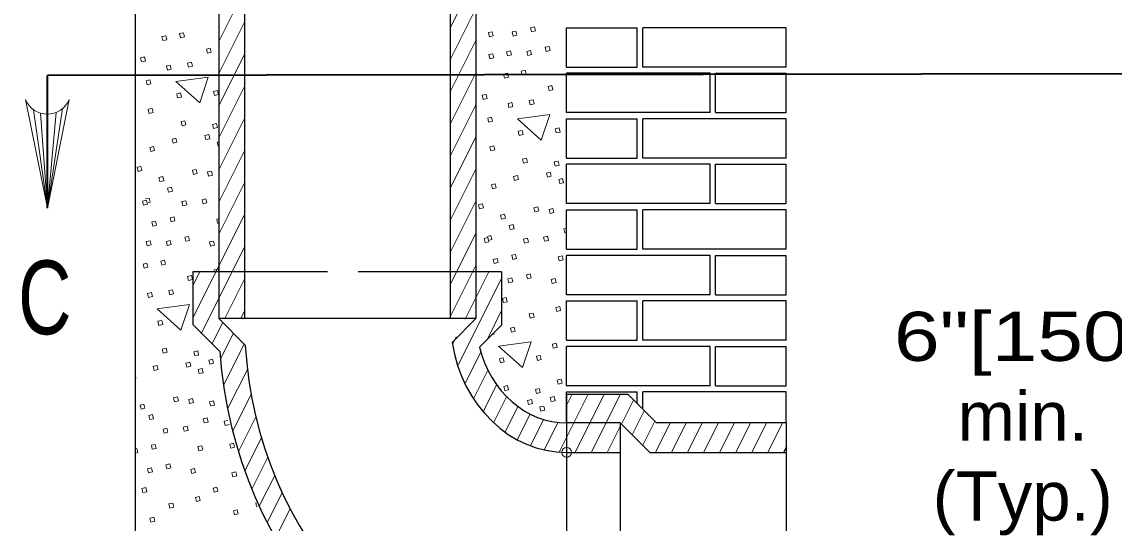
# Model space of a CAD drawing. Extents: x 750.7 to 784.7, y 860.1 to 882.1.
# Drawn here: x 760.221 to 763.779, y 864.968 to 866.601 of the extents above; entities that cross this region are included whole.
import ezdxf
from ezdxf.enums import TextEntityAlignment as Align

# ---------------------------------------------------------------- set-up
doc = ezdxf.new("R2010")
doc.units = 0
doc.header["$LTSCALE"] = 0.064
doc.header["$PDMODE"] = 32
doc.header["$PDSIZE"] = 0.032
doc.linetypes.add('LONG_DASHED', pattern=[7.5, 6, -1.5])
doc.layers.add('1', color=7, linetype='Continuous', lineweight=13)

msp = doc.modelspace()

# ---------------------------------------------------------------- linework, layer by layer
at = {"layer": '1', "lineweight": 25}
for p, q in [((760.59067, 862.95208), (760.59067, 875.03808)), ((760.862, 867.06925), (760.862, 865.6345)), ((760.94567, 867.089), (760.94567, 865.63483)), ((761.7, 866.80892), (761.7, 865.6345)), ((761.61633, 866.72725), (761.61633, 865.63483)), ((762.22558, 866.45333), (762.22558, 866.58133)), ((761.9955, 866.45333), (762.22558, 866.45333)), ((762.71083, 866.30508), (762.71083, 866.43308)), ((762.22558, 866.15675), (762.22558, 866.28483)), ((762.48075, 866.30508), (762.71083, 866.30508)), ((761.9955, 866.15675), (762.22558, 866.15675)), ((762.71083, 866.0085), (762.71083, 866.13658)), ((762.48075, 866.0085), (762.71083, 866.0085)), ((762.22558, 865.86025), (762.22558, 865.98833)), ((761.9955, 865.86025), (762.22558, 865.86025)), ((762.71083, 865.712), (762.71083, 865.84)), ((760.862, 865.78683), (760.77825, 865.78683)), ((760.77942, 865.61358), (760.77942, 865.78683)), ((761.78367, 865.78683), (761.7, 865.78683)), ((761.78367, 865.78683), (761.78367, 865.61317)), ((762.48075, 865.712), (762.71083, 865.712)), ((762.22558, 865.56375), (762.22558, 865.69175)), ((760.77942, 865.61358), (760.86583, 865.52725)), ((761.7, 865.6345), (760.862, 865.6345)), ((760.862, 865.6345), (760.94833, 865.54808)), ((761.7, 865.6345), (761.62242, 865.55683)), ((761.78367, 865.61317), (761.71142, 865.54092)), ((761.9955, 865.56375), (762.22558, 865.56375)), ((762.71083, 865.41542), (762.71083, 865.5435)), ((761.995, 865.3885), (761.995, 865.29225)), ((761.995, 865.3885), (762.19467, 865.3885)), ((762.19467, 865.3885), (762.28842, 865.29475)), ((762.22558, 865.35733), (762.22558, 865.39525)), ((762.24317, 865.34067), (762.24317, 865.39525)), ((762.48075, 865.41542), (762.71083, 865.41542)), ((762.17025, 865.29475), (761.99542, 865.29475)), ((762.17025, 865.29475), (762.17025, 864.331)), ((762.17025, 865.29475), (762.2665, 865.1985)), ((762.71083, 865.29475), (762.28842, 865.29475)), ((762.71083, 865.29475), (762.71083, 864.42725)), ((762.70292, 865.1985), (762.71083, 865.21442)), ((761.99542, 865.1985), (762.17025, 865.1985)), ((762.2665, 865.1985), (762.71083, 865.1985))]:
    msp.add_line(p, q, dxfattribs=at)
at = {"layer": '1'}
for p, q in [((761.61633, 866.58133), (761.7, 866.74875)), ((760.862, 866.53667), (760.94567, 866.704)), ((761.61633, 866.47675), (761.7, 866.64417)), ((760.862, 866.432), (760.94567, 866.59942)), ((761.61633, 866.37217), (761.7, 866.53958)), ((760.862, 866.32742), (760.94567, 866.49483)), ((761.61633, 866.26758), (761.7, 866.43492)), ((760.862, 866.22283), (760.94567, 866.39025)), ((760.25917, 866.31417), (760.30408, 865.9935)), ((760.35367, 866.31792), (760.30408, 865.9935)), ((761.61633, 866.163), (761.7, 866.33033)), ((760.28142, 866.30325), (760.30408, 865.9935)), ((760.33283, 866.30567), (760.30408, 865.9935)), ((760.30408, 866.3), (760.30408, 865.9935)), ((760.862, 866.11825), (760.94567, 866.28558)), ((761.61633, 866.05833), (761.7, 866.22575)), ((760.862, 866.01358), (760.94567, 866.181)), ((761.61633, 865.95375), (761.7, 866.12117)), ((760.862, 865.909), (760.94567, 866.07642)), ((760.6235, 866.02392), (760.63567, 866.02683)), ((761.61633, 865.84917), (761.7, 866.01658)), ((760.77825, 865.637), (760.94567, 865.97183)), ((761.61633, 865.74458), (761.7, 865.91192)), ((761.73617, 865.902), (761.74833, 865.90483)), ((760.805, 865.58583), (760.94567, 865.86717)), ((760.77825, 865.74158), (760.80092, 865.78683)), ((760.86008, 865.79567), (760.862, 865.78792)), ((761.61633, 865.63992), (761.7, 865.80733)), ((761.66508, 865.63292), (761.74208, 865.78683)), ((760.88158, 865.6345), (760.94567, 865.76258)), ((761.641, 865.48), (761.78367, 865.7655)), ((760.93433, 865.63533), (760.94567, 865.658)), ((761.73825, 865.56992), (761.78367, 865.66092)), ((760.84092, 865.55317), (760.87408, 865.6195)), ((760.86783, 865.50225), (760.90925, 865.58525)), ((761.62358, 865.54975), (761.636, 865.57458)), ((760.87775, 865.41758), (760.94467, 865.55142)), ((761.66433, 865.42217), (761.71575, 865.525)), ((760.89125, 865.34), (760.95558, 865.46867)), ((761.69208, 865.37308), (761.73875, 865.46633)), ((761.72333, 865.33092), (761.76725, 865.41875)), ((760.90767, 865.26817), (760.96767, 865.38833)), ((761.75767, 865.295), (761.8, 865.37975)), ((761.97133, 865.19942), (762.06467, 865.38617)), ((761.99483, 865.35108), (762.01342, 865.38833)), ((762.02317, 865.1985), (762.11692, 865.38608)), ((762.07542, 865.1985), (762.17033, 865.38833)), ((762.17392, 865.29092), (762.213, 865.36917)), ((761.79475, 865.26467), (761.8365, 865.34817)), ((761.83458, 865.23975), (761.8765, 865.3235)), ((762.20875, 865.25608), (762.2475, 865.3335)), ((760.92642, 865.20117), (760.98317, 865.31458)), ((761.87717, 865.22033), (761.92, 865.306)), ((761.92267, 865.20667), (761.96758, 865.2965)), ((762.12775, 865.1985), (762.16983, 865.28283)), ((762.24383, 865.22167), (762.283, 865.29992)), ((762.28458, 865.1985), (762.33267, 865.29475)), ((762.33692, 865.1985), (762.385, 865.29475)), ((762.38917, 865.1985), (762.43725, 865.29475)), ((762.44142, 865.1985), (762.48958, 865.29475)), ((762.49375, 865.1985), (762.54183, 865.29475)), ((762.546, 865.1985), (762.59417, 865.29475)), ((762.59833, 865.1985), (762.64642, 865.29475)), ((762.65058, 865.1985), (762.69867, 865.29475)), ((760.94733, 865.13825), (761.00133, 865.24642)), ((760.59067, 865.21033), (760.59508, 865.21142)), ((760.97, 865.07908), (761.02183, 865.18283)), ((760.99433, 865.02317), (761.04442, 865.12333)), ((761.02017, 864.97025), (761.06867, 865.06733)), ((761.04733, 864.92008), (761.09458, 865.01458))]:
    msp.add_line(p, q, dxfattribs=at)
at = {"layer": '1', "lineweight": 35}
for p in [(765.90858, 866.43392), (760.30408, 865.9935)]:
    msp.add_line(p, (760.30408, 866.42633), dxfattribs=at)
at = {"layer": '1', "linetype": 'LONG_DASHED', "lineweight": 25}
for p, q in [((761.7, 865.78683), (760.862, 865.78683)), ((761.995, 865.29225), (761.995, 864.3285))]:
    msp.add_line(p, q, dxfattribs=at)
at = {"layer": '1'}
for points in [[(760.74742, 866.56508), (760.75058, 866.55183), (760.738, 866.54883), (760.73483, 866.56208)], [(761.75325, 866.56833), (761.7565, 866.55508), (761.74392, 866.55208), (761.74075, 866.56533)], [(761.83042, 866.57067), (761.83358, 866.55742), (761.82108, 866.55442), (761.81783, 866.56767)], [(761.89058, 866.584), (761.89375, 866.57075), (761.88117, 866.56775), (761.878, 866.581)], [(760.68983, 866.5555), (760.69308, 866.54225), (760.6805, 866.53925), (760.67733, 866.5525)], [(760.83483, 866.51492), (760.83808, 866.50167), (760.8255, 866.49867), (760.82233, 866.51192)], [(761.75483, 866.49675), (761.758, 866.4835), (761.7455, 866.48058), (761.74225, 866.49375)], [(761.81233, 866.50642), (761.81558, 866.49317), (761.803, 866.49017), (761.79983, 866.50342)], [(761.87808, 866.50733), (761.88133, 866.49408), (761.86875, 866.49108), (761.86558, 866.50433)], [(761.93825, 866.52075), (761.94142, 866.5075), (761.92892, 866.5045), (761.92567, 866.51775)], [(760.62025, 866.48625), (760.6235, 866.473), (760.61092, 866.47), (760.60775, 866.48325)], [(760.70425, 866.45992), (760.7075, 866.44667), (760.69492, 866.44367), (760.69175, 866.45692)], [(760.77342, 866.46892), (760.77658, 866.45567), (760.76408, 866.45267), (760.76083, 866.46592)], [(760.82808, 866.42075), (760.72258, 866.40675), (760.80017, 866.33708)], [(761.8025, 866.4335), (761.80575, 866.42025), (761.79317, 866.41725), (761.79, 866.4305)], [(761.86008, 866.44317), (761.86325, 866.42992), (761.85067, 866.42692), (761.8475, 866.44017)], [(760.63817, 866.41183), (760.64133, 866.39858), (760.62875, 866.39558), (760.62558, 866.40883)], [(761.9475, 866.39292), (761.95075, 866.37967), (761.93817, 866.37667), (761.935, 866.38992)], [(760.73783, 866.369), (760.741, 866.35575), (760.72842, 866.35283), (760.72525, 866.366)], [(760.858, 866.37708), (760.86117, 866.36383), (760.84858, 866.36083), (760.84542, 866.37408)], [(761.73292, 866.36425), (761.73617, 866.351), (761.72358, 866.348), (761.72042, 866.36125)], [(760.64533, 866.31883), (760.6485, 866.30558), (760.63592, 866.30258), (760.63275, 866.31583)], [(761.81692, 866.33792), (761.82017, 866.32467), (761.80758, 866.32167), (761.80442, 866.33492)], [(761.88608, 866.34692), (761.88933, 866.33375), (761.87675, 866.33075), (761.8735, 866.34392)], [(760.75192, 866.27858), (760.75508, 866.26533), (760.74258, 866.26233), (760.73933, 866.27558)], [(761.75083, 866.28983), (761.754, 866.27667), (761.74142, 866.27367), (761.73825, 866.28692)], [(761.94075, 866.29883), (761.83533, 866.28475), (761.91283, 866.21508)], [(760.855, 866.26933), (760.85817, 866.25608), (760.84558, 866.25308), (760.84242, 866.26633)], [(761.8505, 866.24708), (761.85367, 866.23383), (761.84108, 866.23083), (761.83792, 866.24408)], [(761.97067, 866.25508), (761.97383, 866.24183), (761.96125, 866.23883), (761.95808, 866.25208)], [(760.72275, 866.22192), (760.72592, 866.20867), (760.71333, 866.20567), (760.71017, 866.21892)], [(760.8295, 866.23325), (760.83267, 866.22), (760.82017, 866.217), (760.81692, 866.23025)], [(760.65017, 866.19475), (760.65333, 866.1815), (760.64075, 866.1785), (760.63758, 866.19175)], [(761.758, 866.19692), (761.76117, 866.18367), (761.74858, 866.18067), (761.74542, 866.19392)], [(761.86458, 866.15658), (761.86775, 866.14333), (761.85525, 866.14033), (761.852, 866.15358)], [(761.96767, 866.14733), (761.97083, 866.13408), (761.95833, 866.13108), (761.95508, 866.14433)], [(760.60867, 866.12983), (760.61183, 866.11658), (760.59925, 866.11358), (760.59608, 866.12683)], [(760.78883, 866.12008), (760.79208, 866.10683), (760.7795, 866.10383), (760.77633, 866.11708)], [(760.83817, 866.11467), (760.84142, 866.10142), (760.82883, 866.09842), (760.82567, 866.11167)], [(761.94217, 866.11125), (761.94533, 866.098), (761.93283, 866.095), (761.92958, 866.10825)], [(760.67983, 866.09642), (760.68308, 866.08325), (760.6705, 866.08025), (760.66733, 866.0935)], [(761.76283, 866.07283), (761.766, 866.05958), (761.75342, 866.05658), (761.75025, 866.06983)], [(761.83542, 866.1), (761.83858, 866.08675), (761.826, 866.08375), (761.82283, 866.097)], [(761.98217, 866.09), (761.98542, 866.07675), (761.97283, 866.07375), (761.96967, 866.087)], [(760.70833, 866.06208), (760.71158, 866.04883), (760.699, 866.04583), (760.69583, 866.05908)], [(760.6265, 866.01992), (760.62975, 866.00667), (760.61717, 866.00375), (760.614, 866.01692)], [(760.75483, 866.01817), (760.758, 866.00492), (760.7455, 866.00192), (760.74225, 866.01517)], [(760.82033, 866.02408), (760.82358, 866.01083), (760.811, 866.00783), (760.80783, 866.02108)], [(761.72133, 866.00783), (761.7245, 865.99458), (761.71192, 865.99158), (761.70875, 866.00483)], [(761.9015, 865.99808), (761.90475, 865.98483), (761.89217, 865.98183), (761.889, 865.99508)], [(760.71658, 865.96542), (760.71975, 865.95217), (760.70717, 865.94917), (760.704, 865.96242)], [(761.79258, 865.9745), (761.79575, 865.96125), (761.78317, 865.95825), (761.78, 865.9715)], [(761.95083, 865.99267), (761.95408, 865.97942), (761.9415, 865.97642), (761.93833, 865.98967)], [(760.65642, 865.952), (760.65958, 865.93875), (760.64708, 865.93575), (760.64383, 865.949)], [(761.821, 865.94017), (761.82425, 865.92692), (761.81167, 865.92392), (761.8085, 865.93717)], [(760.63833, 865.88783), (760.64158, 865.87458), (760.629, 865.87158), (760.62583, 865.88483)], [(760.70408, 865.88875), (760.70733, 865.8755), (760.69475, 865.8725), (760.69158, 865.88575)], [(760.76425, 865.90208), (760.76742, 865.88883), (760.75492, 865.88592), (760.75167, 865.89908)], [(760.845, 865.88675), (760.84825, 865.8735), (760.83567, 865.8705), (760.83242, 865.88375)], [(761.73917, 865.898), (761.74242, 865.88475), (761.72983, 865.88175), (761.72667, 865.895)], [(761.8675, 865.89617), (761.87075, 865.88292), (761.85817, 865.87992), (761.85492, 865.89317)], [(761.933, 865.90217), (761.93625, 865.88892), (761.92367, 865.88592), (761.9205, 865.89917)], [(760.68608, 865.8245), (760.68925, 865.81125), (760.67667, 865.80825), (760.6735, 865.8215)], [(761.76908, 865.83008), (761.77225, 865.81683), (761.75975, 865.81383), (761.7565, 865.82708)], [(761.82925, 865.84342), (761.83242, 865.83017), (761.81983, 865.82717), (761.81667, 865.84042)], [(761.98075, 865.83883), (761.98392, 865.82558), (761.97133, 865.82258), (761.96817, 865.83583)], [(760.6285, 865.81483), (760.63175, 865.80167), (760.61917, 865.79867), (760.616, 865.81192)], [(761.87692, 865.78017), (761.88008, 865.76692), (761.86758, 865.76392), (761.86433, 865.77717)], [(760.7735, 865.77433), (760.77675, 865.76108), (760.76417, 865.75808), (760.761, 865.77133)], [(761.81675, 865.76675), (761.82, 865.7535), (761.80742, 865.7505), (761.80425, 865.76375)], [(761.95767, 865.76475), (761.96092, 865.7515), (761.94833, 865.7485), (761.94517, 865.76175)], [(760.64292, 865.71933), (760.64617, 865.70608), (760.63358, 865.70308), (760.63042, 865.71633)], [(760.71208, 865.72833), (760.71533, 865.71508), (760.70275, 865.71208), (760.69958, 865.72533)], [(760.76675, 865.68017), (760.66133, 865.66617), (760.73883, 865.5965)], [(761.79875, 865.70258), (761.80192, 865.68933), (761.78933, 865.68633), (761.78617, 865.69958)], [(761.97275, 865.67375), (761.97592, 865.6605), (761.96342, 865.6575), (761.96017, 865.67075)], [(761.88625, 865.65233), (761.88942, 865.63908), (761.87683, 865.63608), (761.87367, 865.64933)], [(760.6765, 865.62842), (760.67967, 865.61517), (760.66708, 865.61217), (760.66392, 865.62542)], [(761.82475, 865.60633), (761.828, 865.59308), (761.81542, 865.59017), (761.81225, 865.60333)], [(760.69058, 865.538), (760.69383, 865.52475), (760.68125, 865.52175), (760.678, 865.535)], [(761.87942, 865.55825), (761.774, 865.54417), (761.8515, 865.4745)], [(761.96133, 865.55375), (761.96458, 865.5405), (761.952, 865.5375), (761.94883, 865.55075)], [(760.79367, 865.52875), (760.79683, 865.5155), (760.78433, 865.5125), (760.78108, 865.52575)], [(760.84208, 865.50217), (760.84525, 865.48892), (760.83267, 865.48592), (760.8295, 865.49917)], [(761.78917, 865.5065), (761.79233, 865.49325), (761.77975, 865.49025), (761.77658, 865.5035)], [(761.90933, 865.5145), (761.9125, 865.50125), (761.9, 865.49825), (761.89675, 865.5115)], [(760.66142, 865.48133), (760.66458, 865.46808), (760.65208, 865.46508), (760.64883, 865.47833)], [(760.76817, 865.49258), (760.77142, 865.47942), (760.75883, 865.47642), (760.75558, 865.48967)], [(760.80817, 865.47133), (760.81142, 865.45808), (760.79883, 865.45508), (760.79567, 865.46833)], [(761.97742, 865.43717), (761.98058, 865.42392), (761.96808, 865.42092), (761.96483, 865.43417)], [(761.80325, 865.416), (761.8065, 865.40275), (761.79392, 865.39975), (761.79075, 865.413)], [(761.90633, 865.40675), (761.9095, 865.3935), (761.897, 865.3905), (761.89375, 865.40375)], [(760.61858, 865.35583), (760.62175, 865.34267), (760.60917, 865.33967), (760.606, 865.35283)], [(760.7275, 865.3795), (760.73075, 865.36625), (760.71817, 865.36325), (760.715, 865.3765)], [(760.77683, 865.37408), (760.78008, 865.36083), (760.7675, 865.35783), (760.76433, 865.37108)], [(760.845, 865.366), (760.84817, 865.35283), (760.83567, 865.34983), (760.83242, 865.36308)], [(761.88083, 865.37067), (761.88408, 865.35742), (761.8715, 865.35442), (761.86833, 865.36767)], [(761.95475, 865.38017), (761.95792, 865.367), (761.94533, 865.364), (761.94217, 865.37725)], [(760.647, 865.3215), (760.65025, 865.30825), (760.63767, 865.30525), (760.6345, 865.3185)], [(761.92092, 865.34942), (761.92408, 865.33617), (761.9115, 865.33317), (761.90833, 865.34642)], [(760.759, 865.2835), (760.76225, 865.27025), (760.74967, 865.26725), (760.7465, 865.2805)], [(760.82458, 865.31075), (760.82775, 865.2975), (760.81517, 865.29458), (760.812, 865.30775)], [(760.6935, 865.27758), (760.69675, 865.26433), (760.68417, 865.26133), (760.681, 865.27458)], [(760.65525, 865.22483), (760.65842, 865.21158), (760.64583, 865.20858), (760.64267, 865.22183)], [(760.80675, 865.22025), (760.80992, 865.207), (760.79733, 865.204), (760.79417, 865.21725)], [(760.91058, 865.22833), (760.91375, 865.21508), (760.90117, 865.21208), (760.898, 865.22533)], [(760.64275, 865.14817), (760.646, 865.13492), (760.63342, 865.13192), (760.63025, 865.14517)], [(760.70292, 865.1615), (760.70608, 865.14825), (760.69358, 865.14525), (760.69033, 865.1585)], [(760.78367, 865.14608), (760.78692, 865.13292), (760.77433, 865.12992), (760.77117, 865.14317)], [(760.91775, 865.13533), (760.92092, 865.12217), (760.90833, 865.11917), (760.90517, 865.13242)], [(760.62475, 865.08392), (760.62792, 865.07067), (760.61533, 865.06767), (760.61217, 865.08092)], [(760.85625, 865.08542), (760.85942, 865.07217), (760.84692, 865.06917), (760.84367, 865.08242)], [(760.71225, 865.03375), (760.71542, 865.0205), (760.70283, 865.0175), (760.69967, 865.03075)], [(760.79875, 865.05508), (760.80192, 865.04183), (760.78942, 865.03892), (760.78617, 865.05208)], [(760.92258, 865.01125), (760.92575, 864.99808), (760.91317, 864.99508), (760.91, 865.00833)], [(760.65075, 864.98775), (760.654, 864.9745), (760.64142, 864.9715), (760.63825, 864.98475)]]:
    msp.add_lwpolyline(points, close=True, dxfattribs=at)
at = {"layer": '1', "lineweight": 25}
for points in [[(761.9955, 866.45333), (761.9955, 866.58133), (762.22558, 866.58133)], [(762.71083, 866.45333), (762.71083, 866.58133), (762.24317, 866.58133)], [(762.71083, 866.45333), (762.24317, 866.45333), (762.24317, 866.58133)], [(762.46308, 866.30508), (762.46308, 866.43308), (761.99542, 866.43308)], [(762.46308, 866.30508), (761.99542, 866.30508), (761.99542, 866.43308)], [(762.48075, 866.30508), (762.48075, 866.43308), (762.71083, 866.43308)], [(761.9955, 866.15675), (761.9955, 866.28483), (762.22558, 866.28483)], [(762.71083, 866.15675), (762.71083, 866.28483), (762.24317, 866.28483)], [(762.71083, 866.15675), (762.24317, 866.15675), (762.24317, 866.28483)], [(762.46308, 866.0085), (762.46308, 866.13658), (761.99542, 866.13658)], [(762.46308, 866.0085), (761.99542, 866.0085), (761.99542, 866.13658)], [(762.48075, 866.0085), (762.48075, 866.13658), (762.71083, 866.13658)], [(761.9955, 865.86025), (761.9955, 865.98833), (762.22558, 865.98833)], [(762.71083, 865.86025), (762.71083, 865.98833), (762.24317, 865.98833)], [(762.71083, 865.86025), (762.24317, 865.86025), (762.24317, 865.98833)], [(762.46308, 865.712), (762.46308, 865.84008), (761.99542, 865.84008)], [(762.46308, 865.712), (761.99542, 865.712), (761.99542, 865.84008)], [(762.48075, 865.712), (762.48075, 865.84), (762.71083, 865.84)], [(761.9955, 865.56375), (761.9955, 865.69175), (762.22558, 865.69175)], [(762.71083, 865.56375), (762.71083, 865.69175), (762.24317, 865.69175)], [(762.71083, 865.56375), (762.24317, 865.56375), (762.24317, 865.69175)], [(762.46308, 865.4155), (762.46308, 865.5435), (761.99542, 865.5435)], [(762.46308, 865.4155), (761.99542, 865.4155), (761.99542, 865.5435)], [(762.48075, 865.41542), (762.48075, 865.5435), (762.71083, 865.5435)], [(761.9955, 865.29475), (761.9955, 865.39525), (762.22558, 865.39525)], [(762.71083, 865.29475), (762.71083, 865.39525), (762.24317, 865.39525)]]:
    msp.add_lwpolyline(points, dxfattribs=at)
at = {"layer": '1'}
for points in [[(760.37492, 866.34767), (760.30408, 865.9935), (760.23325, 866.34767)], [(760.862, 866.19617), (760.86017, 866.19567), (760.857, 866.20892), (760.862, 866.21017)], [(760.63567, 866.02683), (760.63883, 866.01358), (760.6325, 866.012)], [(760.862, 865.94533), (760.85867, 865.94458), (760.8555, 865.95783), (760.862, 865.95933)], [(761.99417, 865.91433), (761.98917, 865.91317), (761.986, 865.92642), (761.99417, 865.92833)], [(761.74833, 865.90483), (761.7515, 865.89158), (761.74517, 865.89008)], [(760.84892, 865.78683), (760.8475, 865.79267), (760.86008, 865.79567)], [(761.758, 865.5875), (761.75883, 865.58408), (761.75325, 865.58275)], [(760.59067, 865.4465), (760.592, 865.44092), (760.59067, 865.44058)], [(760.89575, 865.2895), (760.88333, 865.2865), (760.88017, 865.29975), (760.89142, 865.30242)], [(760.59508, 865.21142), (760.59833, 865.19817), (760.59067, 865.19633)], [(760.98783, 865.02275), (760.98575, 865.02225), (760.98258, 865.03542), (760.98342, 865.03567)]]:
    msp.add_lwpolyline(points, dxfattribs=at)
msp.add_arc((760.30398, 866.37626), 0.07644, 202.08782, 337.91395, dxfattribs=at)
at = {"layer": '1', "lineweight": 25}
for centre, major_axis, start_param, end_param in [((761.99543, 865.63447), (0, -1.20726), 4.7839902, 6.2831862), ((761.99543, 865.63449), (0, -0.43594), 4.8913832, 6.2831858), ((761.99543, 865.63449), (0, -0.33972), 4.9913228, 6.28466), ((761.99543, 865.63447), (0, -1.30349), 4.7947684, 6.2831858)]:
    msp.add_ellipse(centre, major_axis=major_axis, ratio=0.869565, start_param=start_param, end_param=end_param, dxfattribs=at)
at = {"layer": '1'}
msp.add_point((761.99542, 865.1985), dxfattribs=at)

# ---------------------------------------------------------------- texts
at = {"layer": '1', "width": 0.75}
msp.add_text('C', height=0.24, dxfattribs=at).set_placement((760.20867, 865.58342))
at = {"layer": '1'}
for s, width, p in [('6"[150]', 1.25, (763.481, 865.49642)), ('min.', 1.05, (763.481, 865.23642)), ('(Typ.)', 1.05, (763.481, 864.97642))]:
    msp.add_text(s, height=0.16, dxfattribs=dict(at, width=width)).set_placement(p, align=Align.CENTER)

doc.saveas('drawing.dxf')
